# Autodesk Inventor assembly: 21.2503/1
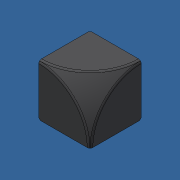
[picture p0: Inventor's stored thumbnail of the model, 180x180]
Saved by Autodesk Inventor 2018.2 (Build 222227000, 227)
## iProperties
Created: 2007-01
Part Number: 21.2503/1
Document SubType Name: Assembly
Designer: Andy Moles
Description: MOUNTING ANGLE 45 G
Stock Number: 21.2503/1 MOUNTING ANGLE 45 G
Author: Andy Moles
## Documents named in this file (5)
- Y:\INVENTOR LIBRARIES\PARTS LIBRARY\FASTENING ELEMENTS\21.2503_1 MOUNTING ANGLE 45 G.iam
- Y:\INVENTOR LIBRARIES\PARTS LIBRARY\FASTENING ELEMENTS\SUBCOMPONENTS\21.1708_2 ANGLE 45 DEG.ipt
- Y:\INVENTOR LIBRARIES\PARTS LIBRARY\FASTENING ELEMENTS\SCREWS CAP\21.1204 M8X25.ipt
- Y:\INVENTOR LIBRARIES\PARTS LIBRARY\FASTENING ELEMENTS\SUBCOMPONENTS\21.1386 SCREW CON ANTI ROT.ipt
- Y:\INVENTOR LIBRARIES\PARTS LIBRARY\FASTENING ELEMENTS\SUBCOMPONENTS\22.1177_1 CAP FOR MOUNTING ANGLE 45 G.ipt
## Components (8 placed, 4 different names)
1. 21.1708_2 ANGLE 45 DEG:1 — Insert:1, Insert:2, Insert:3, Insert:7, Angle:4, Insert:8, Angle:5, Insert:9, Angle:6, Mate:1, Flush:1
2. 21.1204  M8 x 25:1 — Insert:1
3. 21.1204  M8 x 25:2 — Insert:2
4. 21.1204  M8 x 25:3 — Insert:3
5. 21.1386 SCREW CON ANTI ROT:1 — Insert:7, Angle:4
6. 21.1386 SCREW CON ANTI ROT:3 — Insert:9, Angle:6
7. 21.1386 SCREW CON ANTI ROT:2 — Insert:8, Angle:5
8. 22.1177_1 CAP FOR MOUNTING ANGLE 45 G:1 — Mate:1, Flush:1
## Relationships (11: Insert 6, Angle 3, Mate 1, Flush 1)
- Insert:1: 21.1708_2 ANGLE 45 DEG:1 ↔ 21.1204  M8 x 25:1
- Insert:2: 21.1708_2 ANGLE 45 DEG:1 ↔ 21.1204  M8 x 25:2
- Insert:3: 21.1708_2 ANGLE 45 DEG:1 ↔ 21.1204  M8 x 25:3
- Insert:7: 21.1708_2 ANGLE 45 DEG:1 ↔ 21.1386 SCREW CON ANTI ROT:1
- Angle:4: 21.1708_2 ANGLE 45 DEG:1 ↔ 21.1386 SCREW CON ANTI ROT:1
- Insert:8: 21.1708_2 ANGLE 45 DEG:1 ↔ 21.1386 SCREW CON ANTI ROT:2
- Angle:5: 21.1708_2 ANGLE 45 DEG:1 ↔ 21.1386 SCREW CON ANTI ROT:2
- Insert:9: 21.1708_2 ANGLE 45 DEG:1 ↔ 21.1386 SCREW CON ANTI ROT:3
- Angle:6: 21.1708_2 ANGLE 45 DEG:1 ↔ 21.1386 SCREW CON ANTI ROT:3
- Mate:1: 21.1708_2 ANGLE 45 DEG:1 ↔ 22.1177_1 CAP FOR MOUNTING ANGLE 45 G:1
- Flush:1: 21.1708_2 ANGLE 45 DEG:1 ↔ 22.1177_1 CAP FOR MOUNTING ANGLE 45 G:1
